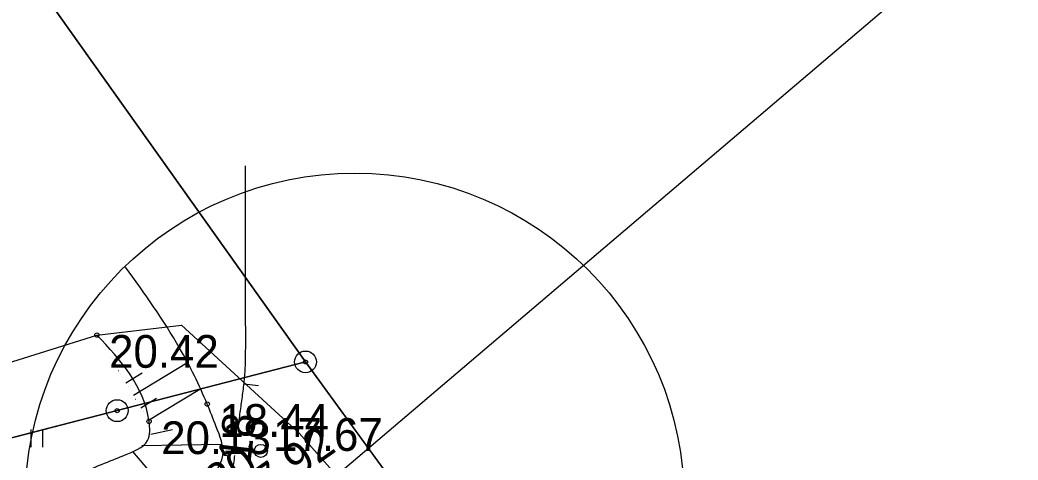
# Model space of a CAD drawing. Extents: x 521824 to 524158, y 294774 to 296228.
# Drawn here: x 522290.61 to 522324.88, y 296057.55 to 296072.68 of the extents above; entities that cross this region are included whole.
import ezdxf

# ---------------------------------------------------------------- set-up
doc = ezdxf.new("R2010")
doc.units = 0
for name, color, linetype in [('Geolite Projekts', 7, 'Continuous'), ('HIDG_AATZ_####_TKST_#', 7, 'Continuous'), ('HIDG_ELEM_####_####_#', 7, 'Continuous'), ('HIDG_HORZ_####_TKST_#', 7, 'Continuous'), ('HIDG_HORZ_RESN_####_#', 7, 'Continuous'), ('HIDG_PLIN_####_####_#', 7, 'Continuous'), ('HIDT_CAUR_####_TKST_#', 7, 'Continuous'), ('RAMI_UZMR_####_####_#', 7, 'Continuous'), ('RELJ_AATZ_####_TKST_#', 7, 'Continuous'), ('RELJ_ELEM_####_####_#', 7, 'Continuous'), ('RELJ_NOGA_####_####_#', 7, 'Continuous'), ('ROBZ_IERR_####_####_#', 7, 'Continuous'), ('ROBZ_ROBP_####_####_#', 7, 'Continuous'), ('ROBZ_UZMR_####_####_#', 7, 'Continuous'), ('TERT_ELEM_####_####_#', 7, 'Continuous')]:
    doc.layers.add(name, color=color, linetype=linetype)

msp = doc.modelspace()

# ---------------------------------------------------------------- linework, layer by layer
at = {"layer": 'Geolite Projekts'}
msp.add_lwpolyline([(522179.429, 296124.387), (522380.628, 296124.387), (522299.308, 296055.162)], dxfattribs=at)
msp.add_circle((522302.107, 296056.094), 11.318, dxfattribs=at)
at = {"layer": 'HIDG_ELEM_####_####_#'}
msp.add_circle((522298.887, 296057.867), 0.225, dxfattribs=at)
at = {"layer": 'HIDG_HORZ_RESN_####_#'}
msp.add_line((522298.802, 296060.107), (522298.305, 296060.162), dxfattribs=at)
for points in [[(522298.138, 296058.929), (522298.213, 296059.458), (522298.285, 296059.988), (522298.338, 296060.519), (522298.359, 296061.052), (522298.359, 296062.665), (522298.359, 296067.665)], [(522296.969, 296055.958), (522297.048, 296056.062), (522297.074, 296056.097), (522297.101, 296056.132), (522297.159, 296056.2), (522297.287, 296056.329), (522297.354, 296056.392), (522297.422, 296056.453), (522297.558, 296056.577), (522297.68, 296056.701), (522297.737, 296056.768), (522297.79, 296056.839), (522297.87, 296056.988), (522297.913, 296057.149), (522297.989, 296057.712)]]:
    msp.add_spline(points, degree=3, dxfattribs=at)
at = {"layer": 'HIDG_PLIN_####_####_#'}
msp.add_spline([(522371.644, 295960.784), (522368.316, 295964.419), (522361.623, 295972.484), (522354.568, 295982.304), (522351.14, 295981.353), (522353.628, 295983.369), (522349.258, 295989.963), (522348.612, 295994.653), (522338.197, 296003.541), (522326.066, 296020.438), (522316.898, 296033.274), (522306.811, 296047.683), (522300.907, 296055.765), (522298.65, 296054.773), (522297.679, 296054.56), (522296.95, 296056.439), (522297.579, 296057.714), (522297.352, 296058.697), (522297.043, 296059.475), (522296.096, 296061.4), (522294.24, 296064.18)], degree=3, dxfattribs=at)
at = {"layer": 'RAMI_UZMR_####_####_#'}
msp.add_lwpolyline([(522238.336, 296053.36), (522285.718, 296059.481), (522293.257, 296061.848), (522296.155, 296062.191), (522300.201, 296058.476), (522312.508, 296044.556), (522328.24, 296022.822), (522349.854, 295994.636), (522373.592, 295961.698), (522362.138, 295957.162), (522349.174, 295950.882), (522342.278, 295948.544), (522332.736, 295938.071), (522327.686, 295933.811), (522322.022, 295927.668), (522307.813, 295919.973), (522290.212, 295909.174), (522273.707, 295894.679), (522210.195, 295852.819)], dxfattribs=at)
at = {"layer": 'RELJ_ELEM_####_####_#'}
for centre in [(522293.257, 296061.848), (522297.043, 296059.475), (522295.046, 296058.882)]:
    msp.add_circle(centre, 0.075, dxfattribs=at)
at = {"layer": 'RELJ_NOGA_####_####_#'}
for p, q in [((522293.294, 296061.786), (522293.294, 296061.786)), ((522293.473, 296061.489), (522293.474, 296061.49)), ((522293.552, 296061.358), (522293.553, 296061.359)), ((522293.732, 296061.061), (522293.732, 296061.061)), ((522293.811, 296060.93), (522293.811, 296060.93)), ((522294.506, 296059.777), (522296.348, 296060.888)), ((522293.99, 296060.633), (522293.991, 296060.634)), ((522294.069, 296060.502), (522294.07, 296060.502)), ((522294.248, 296060.205), (522294.812, 296060.545)), ((522294.327, 296060.074), (522294.327, 296060.074)), ((522295.023, 296058.92), (522296.791, 296059.987)), ((522294.585, 296059.646), (522294.586, 296059.646)), ((522294.765, 296059.349), (522295.306, 296059.675)), ((522294.844, 296059.217), (522294.844, 296059.218)), ((522295.091, 296058.784), (522295.092, 296058.784)), ((522295.106, 296058.442), (522295.845, 296058.602)), ((522294.803, 296058.057), (522297.517, 296058.096)), ((522295.047, 296058.301), (522295.048, 296058.301)), ((522294.236, 296057.736), (522294.236, 296057.736)), ((522294.376, 296057.799), (522294.376, 296057.799)), ((522294.477, 296057.849), (522295.066, 296057.162)), ((522294.678, 296057.968), (522294.679, 296057.967)), ((522293.916, 296057.603), (522293.917, 296057.602))]:
    msp.add_line(p, q, dxfattribs=at)
for points in [[(522293.916, 296057.603), (522294.201, 296057.721), (522294.991, 296058.227), (522295.046, 296058.882), (522293.257, 296061.848)], [(522132.758, 296026.1), (522134.849, 296026.66), (522137.285, 296027.243), (522139.747, 296027.483), (522145.259, 296027.276), (522150.774, 296026.897), (522158.158, 296026.289), (522160.459, 296025.86), (522162.75, 296025.2), (522165.037, 296024.612), (522166.182, 296024.44), (522167.328, 296024.401), (522170.1, 296024.723), (522172.873, 296025.349), (522175.647, 296026.055), (522178.421, 296026.617), (522179.59, 296026.771), (522183.138, 296027.094), (522185.508, 296027.326), (522187.854, 296027.695), (522190.491, 296028.549), (522193.016, 296029.772), (522195.533, 296031.018), (522198.152, 296031.94), (522201.063, 296032.575), (522203.991, 296033.147), (522206.918, 296033.728), (522209.824, 296034.39), (522218.555, 296036.665), (522230.654, 296039.297), (522234.292, 296040.122), (522234.798, 296040.428), (522235.211, 296040.939), (522235.598, 296041.446), (522236.024, 296041.741), (522236.393, 296041.619), (522236.766, 296041.232), (522237.159, 296040.835), (522237.592, 296040.682), (522240.148, 296041.069), (522242.728, 296041.565), (522245.324, 296042.053), (522247.926, 296042.418), (522249.052, 296042.513), (522252.447, 296042.661), (522254.709, 296042.778), (522256.954, 296043.028), (522258.567, 296043.588), (522260.064, 296044.512), (522261.55, 296045.468), (522263.132, 296046.129), (522264.319, 296046.311), (522265.535, 296046.383), (522266.747, 296046.475), (522267.925, 296046.72), (522275.703, 296049.333), (522280.583, 296051.148), (522284.165, 296052.343), (522285.948, 296052.965), (522286.827, 296053.314), (522287.693, 296053.701), (522289.993, 296055.157), (522292.172, 296056.808), (522293.116, 296057.277), (522293.916, 296057.603)]]:
    msp.add_spline(points, degree=3, dxfattribs=at)
at = {"layer": 'ROBZ_IERR_####_####_#'}
for points in [[(522380.027, 296030.421), (522347.967, 296016.117), (522337.144, 296010.443), (522300.416, 296060.924), (522268.4, 296105.967)], [(521982.721, 296071.944), (522030.783, 296022.794), (522033.554, 296023.535), (522231.747, 296043.148), (522293.95, 296059.25), (522300.416, 296060.924), (522337.144, 296010.443), (522362.112, 295976.434), (522359.108, 295971.285), (522349.756, 295955.259), (522172.848, 295833.392), (522168.097, 295830.304), (522159.466, 295824.695), (522157.572, 295823.464), (522100.03, 295786.069), (522037.633, 295748.407), (521945.66, 295684.513), (521914.938, 295661.444)]]:
    msp.add_lwpolyline(points, dxfattribs=at)
at = {"layer": 'ROBZ_ROBP_####_####_#'}
for centre, radius in [((522300.416, 296060.924), 0.375), ((522300.416, 296060.924), 0.0702), ((522293.95, 296059.25), 0.375), ((522293.95, 296059.25), 0.0702)]:
    msp.add_circle(centre, radius, dxfattribs=at)
at = {"layer": 'ROBZ_UZMR_####_####_#'}
msp.add_lwpolyline([(522268.4, 296105.967), (522300.416, 296060.924), (522293.95, 296059.25), (522231.747, 296043.148), (522148.908, 296111.268)], dxfattribs=at)
at = {"layer": 'TERT_ELEM_####_####_#'}
for p, q in [((522291, 296058), (522291, 296058.6)), ((522291.4, 296058), (522291.4, 296058.6))]:
    msp.add_line(p, q, dxfattribs=at)

# ---------------------------------------------------------------- texts
at = {"layer": 'HIDG_AATZ_####_TKST_#'}
msp.add_text(' 17.67', height=1.125, dxfattribs=at).set_placement((522298.887, 296057.867))
at = {"layer": 'HIDG_HORZ_####_TKST_#'}
msp.add_text('18', height=1.125, rotation=83.2941, dxfattribs=at).set_placement((522298.528, 296057.444))
at = {"layer": 'HIDT_CAUR_####_TKST_#'}
for s, p in [('t17.92', (522298.098, 296055.472)), ('b d530', (522295.095, 296054.557))]:
    msp.add_text(s, height=1.125, rotation=35.0919, dxfattribs=at).set_placement(p)
at = {"layer": 'RELJ_AATZ_####_TKST_#'}
for s, p in [(' 20.42', (522293.257, 296060.723)), (' 18.44', (522297.043, 296058.35)), (' 20.13', (522295.046, 296057.757))]:
    msp.add_text(s, height=1.125, dxfattribs=at).set_placement(p)

doc.saveas('drawing.dxf')
